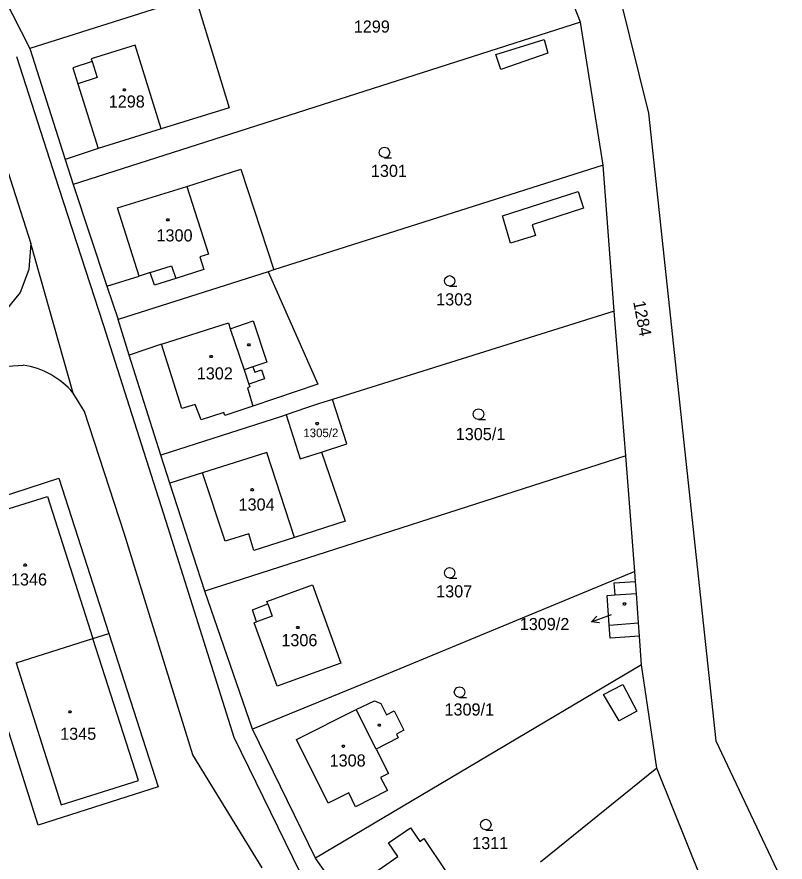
# Model space of a CAD drawing. Extents: x -621797 to -620972, y -1175539 to -1174697.
# Drawn here: x -621620.7 to -621513, y -1175362.6 to -1175244 of the extents above; entities that cross this region are included whole.
import ezdxf

# ---------------------------------------------------------------- set-up
doc = ezdxf.new("R2010")
doc.units = 0
for name, color, linetype in [('INZ mimo EON - nadz', 7, 'Continuous'), ('Rozvod plynu EON', 7, 'Continuous'), ('SDEL EON', 7, 'Continuous'), ('SDEL EON - popis', 7, 'Continuous'), ('Silnoproud EON', 7, 'Continuous'), ('Silnoproud EON - popis', 7, 'Continuous')]:
    doc.layers.add(name, color=color, linetype=linetype)

msp = doc.modelspace()

# ---------------------------------------------------------------- linework, layer by layer
at = {"layer": 'INZ mimo EON - nadz'}
msp.add_line((-621540.109, -1175328.866), (-621537.29, -1175327.84), dxfattribs=at)
msp.add_lwpolyline([(-621538.998, -1175328.994), (-621540.109, -1175328.866), (-621539.34, -1175328.054)], dxfattribs=at)
at = {"layer": 'Rozvod plynu EON'}
for points in [[(-621605.53, -1175254.06), (-621605.44, -1175254.21), (-621605.53, -1175254.36), (-621605.71, -1175254.36), (-621605.8, -1175254.21), (-621605.71, -1175254.06)], [(-621599.45, -1175272.3), (-621599.36, -1175272.45), (-621599.45, -1175272.6), (-621599.63, -1175272.6), (-621599.72, -1175272.45), (-621599.63, -1175272.3)], [(-621588.06, -1175289.83), (-621587.97, -1175289.98), (-621588.06, -1175290.13), (-621588.24, -1175290.13), (-621588.33, -1175289.98), (-621588.24, -1175289.83)], [(-621593.37, -1175291.47), (-621593.28, -1175291.62), (-621593.37, -1175291.77), (-621593.55, -1175291.77), (-621593.64, -1175291.62), (-621593.55, -1175291.47)], [(-621578.49, -1175300.9), (-621578.4, -1175301.05), (-621578.49, -1175301.2), (-621578.67, -1175301.2), (-621578.76, -1175301.05), (-621578.67, -1175300.9)], [(-621587.6, -1175310.18), (-621587.51, -1175310.33), (-621587.6, -1175310.48), (-621587.78, -1175310.48), (-621587.87, -1175310.33), (-621587.78, -1175310.18)], [(-621619.44, -1175320.75), (-621619.35, -1175320.9), (-621619.44, -1175321.05), (-621619.62, -1175321.05), (-621619.71, -1175320.9), (-621619.62, -1175320.75)], [(-621535.39, -1175326.21), (-621535.3, -1175326.36), (-621535.39, -1175326.51), (-621535.57, -1175326.51), (-621535.66, -1175326.36), (-621535.57, -1175326.21)], [(-621581.21, -1175329.51), (-621581.12, -1175329.66), (-621581.21, -1175329.81), (-621581.39, -1175329.81), (-621581.48, -1175329.66), (-621581.39, -1175329.51)], [(-621613.15, -1175341.36), (-621613.06, -1175341.51), (-621613.15, -1175341.66), (-621613.33, -1175341.66), (-621613.42, -1175341.51), (-621613.33, -1175341.36)], [(-621569.78, -1175343.22), (-621569.69, -1175343.37), (-621569.78, -1175343.52), (-621569.96, -1175343.52), (-621570.05, -1175343.37), (-621569.96, -1175343.22)], [(-621574.82, -1175346.19), (-621574.73, -1175346.34), (-621574.82, -1175346.49), (-621575, -1175346.49), (-621575.09, -1175346.34), (-621575, -1175346.19)]]:
    msp.add_lwpolyline(points, close=True, dxfattribs=at)
at = {"layer": 'SDEL EON'}
for points in [[(-621569.14, -1175263.72), (-621569.52, -1175263.62), (-621569.79, -1175263.35), (-621569.89, -1175262.98), (-621569.79, -1175262.61), (-621569.52, -1175262.34), (-621569.15, -1175262.24), (-621568.78, -1175262.34), (-621568.51, -1175262.61), (-621568.41, -1175262.99), (-621568.51, -1175263.37), (-621568.78, -1175263.64), (-621569.16, -1175263.74), (-621568.16, -1175263.74)], [(-621559.99, -1175281.76), (-621560.37, -1175281.66), (-621560.64, -1175281.39), (-621560.74, -1175281.02), (-621560.64, -1175280.65), (-621560.37, -1175280.38), (-621560, -1175280.28), (-621559.63, -1175280.38), (-621559.36, -1175280.65), (-621559.26, -1175281.03), (-621559.36, -1175281.41), (-621559.63, -1175281.68), (-621560.01, -1175281.78), (-621559.01, -1175281.78)], [(-621555.95, -1175300.47), (-621556.33, -1175300.37), (-621556.6, -1175300.1), (-621556.7, -1175299.73), (-621556.6, -1175299.36), (-621556.33, -1175299.09), (-621555.96, -1175298.99), (-621555.59, -1175299.09), (-621555.32, -1175299.36), (-621555.22, -1175299.74), (-621555.32, -1175300.12), (-621555.59, -1175300.39), (-621555.97, -1175300.49), (-621554.97, -1175300.49)], [(-621559.99, -1175322.74), (-621560.37, -1175322.64), (-621560.64, -1175322.37), (-621560.74, -1175322), (-621560.64, -1175321.63), (-621560.37, -1175321.36), (-621560, -1175321.26), (-621559.63, -1175321.36), (-621559.36, -1175321.63), (-621559.26, -1175322.01), (-621559.36, -1175322.39), (-621559.63, -1175322.66), (-621560.01, -1175322.76), (-621559.01, -1175322.76)], [(-621558.6, -1175339.47), (-621558.98, -1175339.37), (-621559.25, -1175339.1), (-621559.35, -1175338.73), (-621559.25, -1175338.36), (-621558.98, -1175338.09), (-621558.61, -1175337.99), (-621558.24, -1175338.09), (-621557.97, -1175338.36), (-621557.87, -1175338.74), (-621557.97, -1175339.12), (-621558.24, -1175339.39), (-621558.62, -1175339.49), (-621557.62, -1175339.49)], [(-621554.93, -1175358.07), (-621555.31, -1175357.97), (-621555.58, -1175357.7), (-621555.68, -1175357.33), (-621555.58, -1175356.96), (-621555.31, -1175356.69), (-621554.94, -1175356.59), (-621554.57, -1175356.69), (-621554.3, -1175356.96), (-621554.2, -1175357.34), (-621554.3, -1175357.72), (-621554.57, -1175357.99), (-621554.95, -1175358.09), (-621553.95, -1175358.09)]]:
    msp.add_lwpolyline(points, dxfattribs=at)
at = {"layer": 'SDEL EON - popis'}
for p, q in [((-621553.53, -1175249.26), (-621546.77, -1175247.15)), ((-621546.77, -1175247.15), (-621546.22, -1175249.05)), ((-621604.11, -1175247.93), (-621610.29, -1175249.87)), ((-621600.44, -1175259.66), (-621604.11, -1175247.93)), ((-621620.76, -1175249.54), (-621614.79, -1175267.99)), ((-621552.81, -1175251.34), (-621553.53, -1175249.26)), ((-621546.22, -1175249.05), (-621552.81, -1175251.34)), ((-621610.16, -1175250.24), (-621612.85, -1175251.11)), ((-621610.29, -1175249.87), (-621610.16, -1175250.24)), ((-621610.16, -1175250.24), (-621609.42, -1175252.47)), ((-621612.85, -1175251.11), (-621612.15, -1175253.34)), ((-621609.42, -1175252.47), (-621612.15, -1175253.34)), ((-621612.15, -1175253.34), (-621609.3, -1175262.46)), ((-621614.79, -1175267.99), (-621608.59, -1175287.13)), ((-621596.85, -1175267.76), (-621593.83, -1175277.26)), ((-621552.6, -1175271.89), (-621541.97, -1175268.48)), ((-621541.97, -1175268.48), (-621541.25, -1175270.83)), ((-621541.25, -1175270.83), (-621548.44, -1175273.15)), ((-621551.9, -1175274.27), (-621552.6, -1175271.89)), ((-621548.44, -1175273.15), (-621547.97, -1175274.63)), ((-621551.46, -1175275.74), (-621551.9, -1175274.27)), ((-621547.97, -1175274.63), (-621551.46, -1175275.74)), ((-621593.83, -1175277.26), (-621595.05, -1175277.65)), ((-621595.05, -1175277.65), (-621594.47, -1175279.41)), ((-621602.02, -1175279.85), (-621599.01, -1175278.89)), ((-621599.01, -1175278.89), (-621598.39, -1175280.67)), ((-621602.02, -1175279.85), (-621603.54, -1175280.34)), ((-621601.39, -1175281.64), (-621602.02, -1175279.85)), ((-621594.47, -1175279.41), (-621598.39, -1175280.67)), ((-621598.39, -1175280.67), (-621601.39, -1175281.64)), ((-621608.59, -1175287.13), (-621602.55, -1175306.11)), ((-621600.43, -1175289.89), (-621591.04, -1175286.9)), ((-621591.04, -1175286.9), (-621590.76, -1175287.73)), ((-621590.76, -1175287.73), (-621587.54, -1175286.64)), ((-621587.54, -1175286.64), (-621585.64, -1175292.42)), ((-621590.76, -1175287.73), (-621588.83, -1175293.49)), ((-621587.59, -1175293.07), (-621588.83, -1175293.49)), ((-621588.83, -1175293.49), (-621588.15, -1175295.52)), ((-621585.64, -1175292.42), (-621587.59, -1175293.07)), ((-621587.59, -1175293.07), (-621587.34, -1175293.82)), ((-621587.34, -1175293.82), (-621586.38, -1175293.5)), ((-621586.38, -1175293.5), (-621585.95, -1175294.78)), ((-621585.95, -1175294.78), (-621588.15, -1175295.52)), ((-621588.15, -1175295.52), (-621588.02, -1175295.9)), ((-621588.02, -1175295.9), (-621588.36, -1175296.01)), ((-621588.36, -1175296.01), (-621587.61, -1175298.58)), ((-621585.65, -1175305.12), (-621594.64, -1175307.97)), ((-621581.74, -1175317.03), (-621585.65, -1175305.12)), ((-621602.55, -1175306.11), (-621599.8, -1175314.72)), ((-621627.15, -1175314.61), (-621616.41, -1175311.29)), ((-621616.41, -1175311.29), (-621610.03, -1175331.21)), ((-621599.8, -1175314.72), (-621590.25, -1175345.05)), ((-621536.81, -1175325.1), (-621533.82, -1175324.89)), ((-621585.51, -1175326.36), (-621584.88, -1175328.09)), ((-621584.88, -1175328.09), (-621587.07, -1175328.89)), ((-621537.61, -1175329.32), (-621533.52, -1175329.03)), ((-621603.65, -1175351.12), (-621610.03, -1175331.21)), ((-621620.79, -1175334.64), (-621614.47, -1175354.57)), ((-621538.43, -1175339.09), (-621535.71, -1175337.66)), ((-621535.71, -1175337.66), (-621533.73, -1175341.39)), ((-621536.25, -1175342.77), (-621538.43, -1175339.09)), ((-621570.33, -1175346.73), (-621573.11, -1175341.16)), ((-621533.73, -1175341.39), (-621536.25, -1175342.77)), ((-621590.25, -1175345.05), (-621580.99, -1175363.99)), ((-621614.47, -1175354.57), (-621603.65, -1175351.12))]:
    msp.add_line(p, q, dxfattribs=at)
at = {"layer": 'Silnoproud EON'}
for p, q in [((-621540, -1175225.47), (-621532.1, -1175257.48)), ((-621628.06, -1175230.33), (-621618.87, -1175248.42)), ((-621541.66, -1175244.7), (-621544.96, -1175236.09)), ((-621595.72, -1175241.05), (-621618.87, -1175248.42)), ((-621595.72, -1175241.05), (-621590.94, -1175256.75)), ((-621541.66, -1175244.7), (-621612.82, -1175267.49)), ((-621538.49, -1175264.79), (-621541.66, -1175244.7)), ((-621618.87, -1175248.42), (-621613.94, -1175263.96)), ((-621625.14, -1175255.82), (-621618.76, -1175275.78)), ((-621590.94, -1175256.75), (-621600.44, -1175259.66)), ((-621532.1, -1175257.48), (-621522.67, -1175345.56)), ((-621600.44, -1175259.66), (-621609.3, -1175262.46)), ((-621609.3, -1175262.46), (-621613.94, -1175263.96)), ((-621613.94, -1175263.96), (-621612.82, -1175267.49)), ((-621538.49, -1175264.79), (-621584.64, -1175279.48)), ((-621536.91, -1175285.26), (-621538.49, -1175264.79)), ((-621596.85, -1175267.76), (-621589.28, -1175265.36)), ((-621589.28, -1175265.36), (-621584.64, -1175279.48)), ((-621612.82, -1175267.49), (-621608.06, -1175281.78)), ((-621606.58, -1175270.76), (-621596.85, -1175267.76)), ((-621603.54, -1175280.34), (-621606.58, -1175270.76)), ((-621618.76, -1175275.78), (-621619.04, -1175279.41)), ((-621612.8, -1175296.76), (-621618.76, -1175275.78)), ((-621619.04, -1175279.41), (-621620.22, -1175282.63)), ((-621608.06, -1175281.78), (-621603.54, -1175280.34)), ((-621585.45, -1175279.73), (-621606.51, -1175286.44)), ((-621584.64, -1175279.48), (-621585.45, -1175279.73)), ((-621585.45, -1175279.73), (-621578.5, -1175295.51)), ((-621620.22, -1175282.63), (-621622.23, -1175285.15)), ((-621608.06, -1175281.78), (-621606.51, -1175286.44)), ((-621536.91, -1175285.26), (-621576.45, -1175297.66)), ((-621535.31, -1175305.57), (-621536.91, -1175285.26)), ((-621604.93, -1175291.46), (-621606.51, -1175286.44)), ((-621600.43, -1175289.89), (-621604.93, -1175291.46)), ((-621597.56, -1175298.91), (-621600.43, -1175289.89)), ((-621600.5, -1175305.5), (-621604.93, -1175291.46)), ((-621623.94, -1175293.13), (-621619.81, -1175292.84)), ((-621578.5, -1175295.51), (-621587.61, -1175298.58)), ((-621611.21, -1175299.33), (-621612.8, -1175296.76)), ((-621576.45, -1175297.66), (-621578.4, -1175298.27)), ((-621574.43, -1175303.91), (-621576.45, -1175297.66)), ((-621605.64, -1175316.43), (-621611.21, -1175299.33)), ((-621595.68, -1175298.35), (-621597.56, -1175298.91)), ((-621594.85, -1175300.52), (-621595.68, -1175298.35)), ((-621587.61, -1175298.58), (-621591.53, -1175299.9)), ((-621580.07, -1175298.85), (-621582.93, -1175299.84)), ((-621578.4, -1175298.27), (-621580.07, -1175298.85)), ((-621583.6, -1175300.07), (-621600.5, -1175305.5)), ((-621591.69, -1175299.5), (-621594.85, -1175300.52)), ((-621591.53, -1175299.9), (-621591.69, -1175299.5)), ((-621582.93, -1175299.84), (-621583.6, -1175300.07)), ((-621582.93, -1175299.84), (-621580.98, -1175306)), ((-621577.96, -1175305.04), (-621574.43, -1175303.91)), ((-621580.98, -1175306), (-621577.96, -1175305.04)), ((-621577.96, -1175305.04), (-621574.65, -1175314.76)), ((-621599.24, -1175309.39), (-621600.5, -1175305.5)), ((-621535.31, -1175305.57), (-621594.33, -1175324.58)), ((-621534.04, -1175321.82), (-621535.31, -1175305.57)), ((-621631.39, -1175314.13), (-621614.79, -1175308.7)), ((-621614.79, -1175308.7), (-621607.8, -1175330.49)), ((-621594.64, -1175307.97), (-621599.24, -1175309.39)), ((-621591.48, -1175317.56), (-621594.64, -1175307.97)), ((-621594.33, -1175324.58), (-621599.24, -1175309.39)), ((-621574.65, -1175314.76), (-621581.74, -1175317.03)), ((-621596.02, -1175347.54), (-621605.64, -1175316.43)), ((-621588.17, -1175316.5), (-621591.48, -1175317.56)), ((-621587.45, -1175318.87), (-621588.17, -1175316.5)), ((-621581.74, -1175317.03), (-621587.45, -1175318.87)), ((-621534.04, -1175321.82), (-621568.33, -1175336.03)), ((-621533.94, -1175323.19), (-621534.04, -1175321.82)), ((-621585.64, -1175326), (-621579.25, -1175323.69)), ((-621579.25, -1175323.69), (-621575.25, -1175334.66)), ((-621536.93, -1175323.41), (-621533.94, -1175323.19)), ((-621536.81, -1175325.1), (-621536.93, -1175323.41)), ((-621533.82, -1175324.89), (-621533.94, -1175323.19)), ((-621587.64, -1175343.94), (-621594.33, -1175324.58)), ((-621537.91, -1175325.18), (-621536.81, -1175325.1)), ((-621537.61, -1175329.32), (-621537.91, -1175325.18)), ((-621533.52, -1175329.03), (-621533.82, -1175324.89)), ((-621587.66, -1175327.18), (-621585.51, -1175326.36)), ((-621585.51, -1175326.36), (-621585.64, -1175326)), ((-621587.07, -1175328.89), (-621587.66, -1175327.18)), ((-621587.4, -1175329.01), (-621587.07, -1175328.89)), ((-621584.17, -1175337.9), (-621587.4, -1175329.01)), ((-621533.38, -1175330.87), (-621533.52, -1175329.03)), ((-621537.47, -1175331.17), (-621537.61, -1175329.32)), ((-621620.79, -1175334.64), (-621610.03, -1175331.21)), ((-621610.03, -1175331.21), (-621607.8, -1175330.49)), ((-621607.8, -1175330.49), (-621600.89, -1175352.02)), ((-621533.38, -1175330.87), (-621537.47, -1175331.17)), ((-621533.09, -1175334.91), (-621533.38, -1175330.87)), ((-621575.25, -1175334.66), (-621584.17, -1175337.9)), ((-621533.09, -1175334.91), (-621578.8, -1175362.02)), ((-621530.94, -1175349.43), (-621533.09, -1175334.91)), ((-621617.7, -1175357.4), (-621624.53, -1175335.83)), ((-621568.33, -1175336.03), (-621587.64, -1175343.94)), ((-621573.11, -1175341.16), (-621570.53, -1175339.98)), ((-621570.53, -1175339.98), (-621569.63, -1175340.34)), ((-621569.63, -1175340.34), (-621568.84, -1175341.91)), ((-621581.47, -1175345.39), (-621573.11, -1175341.16)), ((-621568.84, -1175341.91), (-621567.78, -1175341.37)), ((-621567.78, -1175341.37), (-621566.41, -1175344.06)), ((-621578.8, -1175362.02), (-621587.64, -1175343.94)), ((-621566.41, -1175344.06), (-621567.47, -1175344.62)), ((-621577.04, -1175354.32), (-621581.47, -1175345.39)), ((-621567.21, -1175345.15), (-621570.33, -1175346.73)), ((-621567.47, -1175344.62), (-621567.21, -1175345.15)), ((-621522.67, -1175345.56), (-621512.96, -1175366.06)), ((-621570.33, -1175346.73), (-621568.6, -1175350.18)), ((-621586.28, -1175363.42), (-621596.02, -1175347.54)), ((-621568.6, -1175350.18), (-621569.68, -1175350.71)), ((-621530.94, -1175349.43), (-621547.26, -1175362.6)), ((-621524.21, -1175366.15), (-621530.94, -1175349.43)), ((-621569.68, -1175350.71), (-621568.72, -1175352.53)), ((-621600.89, -1175352.02), (-621617.7, -1175357.4)), ((-621568.72, -1175352.53), (-621573.21, -1175354.83)), ((-621574.12, -1175352.89), (-621577.04, -1175354.32)), ((-621573.21, -1175354.83), (-621574.12, -1175352.89)), ((-621568.56, -1175359.88), (-621565.49, -1175357.77)), ((-621565.49, -1175357.77), (-621564.18, -1175359.68)), ((-621567.27, -1175361.83), (-621568.56, -1175359.88)), ((-621564.18, -1175359.68), (-621563.61, -1175359.29)), ((-621563.61, -1175359.29), (-621560.49, -1175363.95)), ((-621567.3, -1175378.55), (-621578.8, -1175362.02)), ((-621571.12, -1175364.48), (-621567.27, -1175361.83))]:
    msp.add_line(p, q, dxfattribs=at)
msp.add_arc((-621621.574, -1175304.223), 11.519, 40.3825, 81.18956, dxfattribs=at)

# ---------------------------------------------------------------- texts
at = {"layer": 'INZ mimo EON - nadz'}
msp.add_text('1309/2', height=1.7, dxfattribs=at).set_placement((-621550.172, -1175330.03))
at = {"layer": 'Silnoproud EON - popis'}
for s, height, p in [('1299', 1.7, (-621573.447, -1175246.17)), ('1298', 1.7, (-621607.817, -1175256.69)), ('1301', 1.7, (-621571.047, -1175266.42)), ('1300', 1.7, (-621601.117, -1175275.48)), ('1303', 1.7, (-621561.897, -1175284.46)), ('1302', 1.7, (-621595.467, -1175294.85)), ('1305/2', 1.2, (-621580.523, -1175302.95)), ('1305/1', 1.7, (-621559.147, -1175303.37)), ('1304', 1.7, (-621589.607, -1175313.25)), ('1346', 1.7, (-621621.527, -1175323.77)), ('1307', 1.7, (-621561.897, -1175325.44)), ('1309/2', 0.1, (-621535.967, -1175326.71)), ('1306', 1.7, (-621583.607, -1175332.29)), ('1309/1', 1.7, (-621560.727, -1175342.02)), ('1345', 1.7, (-621614.627, -1175345.43)), ('1308', 1.7, (-621576.837, -1175349.18)), ('1311', 1.7, (-621556.837, -1175360.77))]:
    msp.add_text(s, height=height, dxfattribs=at).set_placement(p)
msp.add_text('1284', height=1.7, rotation=280.80662, dxfattribs=at).set_placement((-621534.276, -1175283.956))

doc.saveas('drawing.dxf')
